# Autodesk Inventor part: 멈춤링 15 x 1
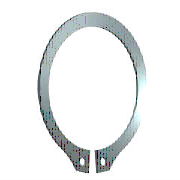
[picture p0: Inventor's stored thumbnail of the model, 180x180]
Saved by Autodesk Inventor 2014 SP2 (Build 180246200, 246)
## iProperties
IsCustomPart: 1
Created: 2012-02
Part Number: 멈춤링 15 x 1
Material: 강철, 연강
Description: 리테이닝 링(C형)
Document SubType Name: Modeling
Standard: KS B 1336
Designer: mduedu
Standards Organization: KS
Language: ko-KR
Size Designation: 15 x 1
Categories: <MemberInstance><Categories><Category DisplayName="샤프트 부품" InternalName="7f7aeb1f-a693-4053-b835-cee3144e0d98" Mnemonic="SHFT"><Category DisplayName="써클립" Inter
Density: 1 g/cm^3
Appearance: 파란색 - 벽 페인트 - 광택
Author: mduedu
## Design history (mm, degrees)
sketch "스케치1"
  geometry: L1 (-6, 0)-(6, 0) reference; L2 (0, 20.189)-(0, -80.536) reference; L3 (-48.09, 0)-(48.09, 0) reference; L4 (-0.425, -14.637)-(-0.425, -18.137); L5 (-0.425, -6.54)-(-0.425, -13.29); L6 (-2.795, 2.1)-(3.672, 2.1); L7 (0.425, -6.54)-(0.425, -13.29); L8 (0.425, -14.637)-(0.425, -18.137); C1 r 0.85 at (-1.7, -16.283); C2 r 0.85 at (1.7, -16.283); A1 r 7.15 centre (0, -7.5) between (0.425, -14.637) and (-0.425, -14.637); A2 r 9.075 centre (0, -6.975) between (4.291, -14.971) and (-4.291, -14.971); A3 r 10.646 centre (0, -7.5) between (-2.023, -17.952) and (-0.425, -18.137); A4 r 1.7 centre (-1.7, -16.283) between (-3.397, -16.376) and (-2.023, -17.952); A5 r 1.7 centre (-5.095, -16.469) between (-3.397, -16.376) and (-4.291, -14.971); A6 r 1.7 centre (5.095, -16.469) between (4.291, -14.971) and (3.397, -16.376); A7 r 1.7 centre (1.7, -16.283) between (2.023, -17.952) and (3.397, -16.376); A8 r 10.646 centre (0, -7.5) between (0.425, -18.137) and (2.023, -17.952)
  constraints: 16 point on circle, 12 end point, 10 centre point, 9 symmetric about line, 5 point on line, 4 tangent, 3 coincident, 2 horizontal, 1 perpendicular, 1 vertical, 5 other
  dimensions: "d0" = 14.3 diameter of A1 (= ND); "d1" = 3.5 distance of L4.end L4.start (= SRB2); "d6" = 0.425 distance between parallel lines of L2 L5 (= 0.25 x SD5); "d7" = 2.1 distance between parallel lines of L6 L3 (= SRB1); "d8" = 0.525 distance of A1.centre A2.centre (= 0.25 x SRB1); "d9" = 1.7 radius of A4 (= SD5); "d10" = 1.7 radius of A5 (= SD5); "d11" = 1.275 distance from line of L4 A4.centre (= 0.75 x SD5); "d12" = 1.7 diameter of C1 (= SD5); "d13" = 1.7 diameter of C2 (= SD5); "d14" = 7.5 distance from line of A1.centre L1 (= 0.5 x WD)
extrude "본체" new body sketch "스케치1" distance "d2" = 1 (= SD); taper "d3" = 0 deg
workaxis "Work Axis1"
workplane "Work Plane1"
body "Solid1"
other parameters: "WD" = 15 (= WDMIN) [user parameter; used in 1 equation term], "SD" = 1 [user parameter; used in 1 equation term], "SRB1" = 2.1 [user parameter; used in 2 equation terms], "ND" = 14.3 [user parameter; used in 1 equation term], "SRB2" = 3.5 [user parameter; used in 1 equation term], "SD5" = 1.7 [user parameter; used in 6 equation terms], "d15" = 0, "d16" = 0, "d17" = 0, "d41" = 0, "d42" = 0, "WDMIN" = 15 [user parameter; used in 1 equation term], "SD3" = 13.8 [user parameter], "WDMAX" = 16 [user parameter]
